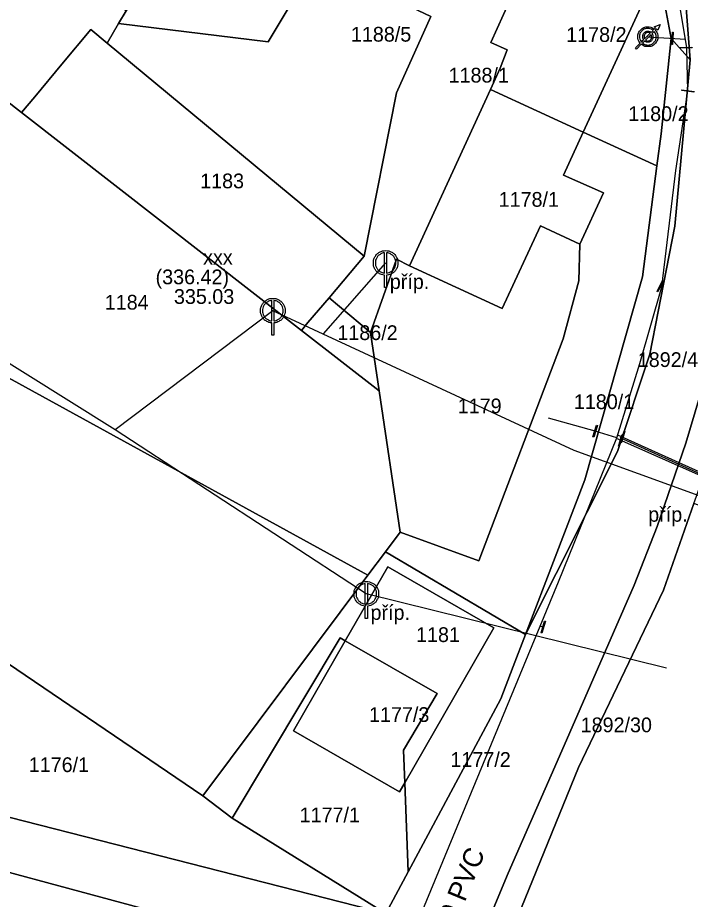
# Model space of a CAD drawing. Extents: x -559956 to -559707, y -1077221 to -1076919.
# Drawn here: x -559891.3 to -559822.9, y -1077119.6 to -1077029.9 of the extents above; entities that cross this region are included whole.
import ezdxf

# ---------------------------------------------------------------- set-up
doc = ezdxf.new("R2010")
doc.units = 0
for name, color, linetype in [('Armatura vodovodní', 7, 'Continuous'), ('Chránička', 7, 'Continuous'), ('Kanalizační přípojka', 7, 'Continuous'), ('Kanalizační šachta', 7, 'Continuous'), ('Odběrné místo', 7, 'Continuous'), ('Parcela-polygon', 7, 'Continuous'), ('Parcela-text', 7, 'Continuous'), ('Popis šachty', 7, 'Continuous'), ('Vodovodní přípojka', 7, 'Continuous'), ('Vodovodní řad', 7, 'Continuous'), ('Řad vodovodní popis', 7, 'Continuous')]:
    doc.layers.add(name, color=color, linetype=linetype)

msp = doc.modelspace()

# ---------------------------------------------------------------- linework, layer by layer
at = {"layer": 'Armatura vodovodní'}
for points in [[(-559824.59, -1077031.341), (-559824.668, -1077032.588), (-559824.746, -1077032.583), (-559824.667, -1077031.336), (-559824.59, -1077031.341)], [(-559823.938, -1077032.879), (-559822.689, -1077032.85), (-559822.687, -1077032.928), (-559823.936, -1077032.957), (-559823.938, -1077032.879)], [(-559823.709, -1077037.185), (-559822.473, -1077037.372), (-559822.485, -1077037.449), (-559823.721, -1077037.262), (-559823.709, -1077037.185)], [(-559826.238, -1077057.707), (-559825.679, -1077056.588), (-559825.61, -1077056.623), (-559826.169, -1077057.742), (-559826.238, -1077057.707)], [(-559832.312, -1077071.349), (-559832.681, -1077072.543), (-559832.756, -1077072.52), (-559832.386, -1077071.326), (-559832.312, -1077071.349)], [(-559829.706, -1077072.277), (-559830.078, -1077073.47), (-559830.152, -1077073.447), (-559829.78, -1077072.254), (-559829.706, -1077072.277)], [(-559829.522, -1077071.957), (-559829.901, -1077073.148), (-559829.976, -1077073.125), (-559829.597, -1077071.934), (-559829.522, -1077071.957)], [(-559838.022, -1077092.445), (-559837.673, -1077091.245), (-559837.598, -1077091.267), (-559837.947, -1077092.467), (-559838.022, -1077092.445)]]:
    msp.add_lwpolyline(points, dxfattribs=at)
at = {"layer": 'Chránička'}
msp.add_line((-559830.034, -1077072.562), (-559821.17, -1077076.58), dxfattribs=at)
at = {"layer": 'Kanalizační přípojka'}
for p, q in [((-559853.84, -1077054.814), (-559860.205, -1077062.042)), ((-559865.31, -1077059.67), (-559881.332, -1077071.786)), ((-559834.678, -1077073.906), (-559865.31, -1077059.67)), ((-559825.272, -1077096.049), (-559855.804, -1077088.477))]:
    msp.add_line(p, q, dxfattribs=at)
for points in [[(-559805.228, -1077048.435), (-559821.569, -1077078.649), (-559834.678, -1077073.906)], [(-559855.804, -1077088.477), (-559881.332, -1077071.786), (-559908.573, -1077054.768)]]:
    msp.add_lwpolyline(points, dxfattribs=at)
at = {"layer": 'Kanalizační šachta'}
for points in [[(-559853.943, -1077055.849), (-559853.943, -1077053.776)], [(-559853.737, -1077053.776), (-559853.737, -1077055.849)], [(-559853.737, -1077056.062), (-559853.737, -1077057.314), (-559853.943, -1077057.314), (-559853.943, -1077056.062)], [(-559865.413, -1077060.705), (-559865.413, -1077058.632)], [(-559865.207, -1077058.632), (-559865.207, -1077060.705)], [(-559865.207, -1077060.918), (-559865.207, -1077062.17), (-559865.413, -1077062.17), (-559865.413, -1077060.918)], [(-559855.907, -1077089.512), (-559855.907, -1077087.439)], [(-559855.701, -1077087.439), (-559855.701, -1077089.512)], [(-559855.701, -1077089.725), (-559855.701, -1077090.977), (-559855.907, -1077090.977), (-559855.907, -1077089.725)]]:
    msp.add_lwpolyline(points, dxfattribs=at)
for points in [[(-559853.943, -1077056.062), (-559854.201, -1077056.044), (-559854.463, -1077055.898), (-559854.76, -1077055.734), (-559854.925, -1077055.437), (-559855.09, -1077055.139), (-559855.09, -1077054.814), (-559855.09, -1077054.487), (-559854.922, -1077054.187), (-559854.753, -1077053.886), (-559854.455, -1077053.725), (-559854.157, -1077053.564), (-559853.84, -1077053.564), (-559853.525, -1077053.564), (-559853.226, -1077053.725), (-559852.927, -1077053.886), (-559852.758, -1077054.187), (-559852.59, -1077054.487), (-559852.59, -1077054.814), (-559852.59, -1077055.139), (-559852.755, -1077055.437), (-559852.92, -1077055.734), (-559853.217, -1077055.898), (-559853.479, -1077056.044), (-559853.737, -1077056.062)], [(-559853.943, -1077053.776), (-559854.14, -1077053.793), (-559854.355, -1077053.908), (-559854.604, -1077054.043), (-559854.743, -1077054.293), (-559854.882, -1077054.543), (-559854.882, -1077054.814), (-559854.882, -1077055.085), (-559854.746, -1077055.332), (-559854.609, -1077055.578), (-559854.36, -1077055.715), (-559854.148, -1077055.835), (-559853.943, -1077055.849)], [(-559853.737, -1077055.849), (-559853.532, -1077055.835), (-559853.318, -1077055.715), (-559853.071, -1077055.578), (-559852.934, -1077055.332), (-559852.798, -1077055.085), (-559852.798, -1077054.814), (-559852.798, -1077054.543), (-559852.938, -1077054.293), (-559853.078, -1077054.043), (-559853.327, -1077053.908), (-559853.54, -1077053.793), (-559853.737, -1077053.776)], [(-559865.413, -1077060.918), (-559865.671, -1077060.9), (-559865.933, -1077060.754), (-559866.23, -1077060.59), (-559866.395, -1077060.293), (-559866.56, -1077059.995), (-559866.56, -1077059.67), (-559866.56, -1077059.343), (-559866.392, -1077059.043), (-559866.223, -1077058.742), (-559865.925, -1077058.581), (-559865.627, -1077058.42), (-559865.31, -1077058.42), (-559864.995, -1077058.42), (-559864.696, -1077058.581), (-559864.397, -1077058.742), (-559864.228, -1077059.043), (-559864.06, -1077059.343), (-559864.06, -1077059.67), (-559864.06, -1077059.995), (-559864.225, -1077060.293), (-559864.39, -1077060.59), (-559864.687, -1077060.754), (-559864.949, -1077060.9), (-559865.207, -1077060.918)], [(-559865.413, -1077058.632), (-559865.61, -1077058.649), (-559865.825, -1077058.764), (-559866.074, -1077058.899), (-559866.213, -1077059.149), (-559866.352, -1077059.399), (-559866.352, -1077059.67), (-559866.352, -1077059.941), (-559866.216, -1077060.188), (-559866.079, -1077060.434), (-559865.83, -1077060.571), (-559865.618, -1077060.691), (-559865.413, -1077060.705)], [(-559865.207, -1077060.705), (-559865.002, -1077060.691), (-559864.788, -1077060.571), (-559864.541, -1077060.434), (-559864.404, -1077060.188), (-559864.268, -1077059.941), (-559864.268, -1077059.67), (-559864.268, -1077059.399), (-559864.408, -1077059.149), (-559864.548, -1077058.899), (-559864.797, -1077058.764), (-559865.01, -1077058.649), (-559865.207, -1077058.632)], [(-559855.907, -1077089.725), (-559856.165, -1077089.707), (-559856.427, -1077089.561), (-559856.724, -1077089.397), (-559856.889, -1077089.1), (-559857.054, -1077088.802), (-559857.054, -1077088.477), (-559857.054, -1077088.15), (-559856.886, -1077087.85), (-559856.717, -1077087.549), (-559856.419, -1077087.388), (-559856.121, -1077087.227), (-559855.804, -1077087.227), (-559855.489, -1077087.227), (-559855.19, -1077087.388), (-559854.891, -1077087.549), (-559854.722, -1077087.85), (-559854.554, -1077088.15), (-559854.554, -1077088.477), (-559854.554, -1077088.802), (-559854.719, -1077089.1), (-559854.884, -1077089.397), (-559855.181, -1077089.561), (-559855.443, -1077089.707), (-559855.701, -1077089.725)], [(-559855.907, -1077087.439), (-559856.104, -1077087.456), (-559856.319, -1077087.571), (-559856.568, -1077087.706), (-559856.707, -1077087.956), (-559856.846, -1077088.206), (-559856.846, -1077088.477), (-559856.846, -1077088.748), (-559856.71, -1077088.995), (-559856.573, -1077089.241), (-559856.324, -1077089.378), (-559856.112, -1077089.498), (-559855.907, -1077089.512)], [(-559855.701, -1077089.512), (-559855.496, -1077089.498), (-559855.282, -1077089.378), (-559855.035, -1077089.241), (-559854.898, -1077088.995), (-559854.762, -1077088.748), (-559854.762, -1077088.477), (-559854.762, -1077088.206), (-559854.902, -1077087.956), (-559855.042, -1077087.706), (-559855.291, -1077087.571), (-559855.504, -1077087.456), (-559855.701, -1077087.439)]]:
    msp.add_open_spline(points, degree=3, dxfattribs=at)
at = {"layer": 'Odběrné místo'}
for points in [[(-559826.528, -1077031.033), (-559826.4, -1077030.905)], [(-559826.4, -1077030.905), (-559826.518, -1077030.794), (-559825.931, -1077030.553), (-559826.153, -1077031.139), (-559826.29, -1077031.01), (-559826.421, -1077031.139)], [(-559827.506, -1077032.013), (-559826.943, -1077031.449)], [(-559826.851, -1077031.571), (-559827.419, -1077032.14)], [(-559826.849, -1077031.355), (-559826.647, -1077031.152)], [(-559826.539, -1077031.259), (-559826.748, -1077031.467)], [(-559827.842, -1077032.564), (-559828.33, -1077033.053), (-559828.431, -1077032.941), (-559827.948, -1077032.456)], [(-559827.828, -1077032.337), (-559827.609, -1077032.116)], [(-559827.512, -1077032.234), (-559827.722, -1077032.444)]]:
    msp.add_lwpolyline(points, dxfattribs=at)
for points in [[(-559827.948, -1077032.456), (-559828.188, -1077032.179), (-559828.188, -1077031.803), (-559828.188, -1077031.386), (-559827.893, -1077031.091), (-559827.598, -1077030.796), (-559827.179, -1077030.796), (-559826.804, -1077030.796), (-559826.528, -1077031.033)], [(-559826.647, -1077031.152), (-559826.874, -1077030.963), (-559827.179, -1077030.963), (-559827.528, -1077030.963), (-559827.774, -1077031.209), (-559828.02, -1077031.455), (-559828.02, -1077031.803), (-559828.02, -1077032.11), (-559827.828, -1077032.337)], [(-559826.421, -1077031.139), (-559826.171, -1077031.42), (-559826.171, -1077031.803), (-559826.171, -1077032.221), (-559826.466, -1077032.515), (-559826.761, -1077032.81), (-559827.179, -1077032.81), (-559827.562, -1077032.81), (-559827.842, -1077032.564)], [(-559827.722, -1077032.444), (-559827.493, -1077032.642), (-559827.179, -1077032.642), (-559826.831, -1077032.642), (-559826.584, -1077032.396), (-559826.338, -1077032.151), (-559826.338, -1077031.803), (-559826.338, -1077031.489), (-559826.539, -1077031.259)], [(-559827.609, -1077032.116), (-559827.617, -1077032.1), (-559827.624, -1077032.084), (-559827.687, -1077031.957), (-559827.687, -1077031.815), (-559827.687, -1077031.548), (-559827.543, -1077031.397), (-559827.399, -1077031.245), (-559827.172, -1077031.245), (-559827.024, -1077031.245), (-559826.904, -1077031.316), (-559826.875, -1077031.334), (-559826.849, -1077031.355)], [(-559826.943, -1077031.449), (-559826.96, -1077031.434), (-559826.98, -1077031.422), (-559827.065, -1077031.369), (-559827.172, -1077031.369), (-559827.322, -1077031.369), (-559827.431, -1077031.472), (-559827.54, -1077031.575), (-559827.54, -1077031.818), (-559827.54, -1077031.929), (-559827.506, -1077032.013)], [(-559826.748, -1077031.467), (-559826.733, -1077031.491), (-559826.721, -1077031.515), (-559826.659, -1077031.642), (-559826.659, -1077031.803), (-559826.659, -1077031.967), (-559826.725, -1077032.095), (-559826.791, -1077032.224), (-559826.912, -1077032.291), (-559827.032, -1077032.357), (-559827.173, -1077032.357), (-559827.324, -1077032.357), (-559827.444, -1077032.284), (-559827.48, -1077032.261), (-559827.512, -1077032.234)], [(-559827.419, -1077032.14), (-559827.319, -1077032.235), (-559827.174, -1077032.235), (-559827.013, -1077032.235), (-559826.909, -1077032.122), (-559826.805, -1077032.009), (-559826.805, -1077031.802), (-559826.805, -1077031.671), (-559826.849, -1077031.574), (-559826.851, -1077031.572), (-559826.851, -1077031.571)]]:
    msp.add_open_spline(points, degree=3, dxfattribs=at)
at = {"layer": 'Parcela-polygon'}
for points in [[(-559829.558, -1076918.773), (-559830.97, -1076923.33), (-559832.36, -1076934.35), (-559834.59, -1076966.73), (-559834.66, -1076971.24), (-559834.55, -1076971.98), (-559833.93, -1076976.03), (-559833.04, -1076981.92), (-559829.78, -1076982.61), (-559827.8, -1076995.29), (-559824.54, -1077015.89), (-559823.98, -1077019.58), (-559822.89, -1077034.16), (-559824.42, -1077051.06), (-559826.97, -1077064.1), (-559830.26, -1077074.01), (-559839.63, -1077092.62), (-559840.88, -1077095.88), (-559842.14, -1077099.15), (-559851.55, -1077116.77), (-559853.81, -1077121)], [(-559841.22, -1077123.3), (-559834.22, -1077106.14), (-559825.6, -1077088.11), (-559822.49, -1077079.28), (-559821.5, -1077076.46), (-559817.47, -1077065.01), (-559816.41, -1077060.26), (-559815.75, -1077057.31), (-559812.17, -1077041.3), (-559812.41, -1077037.94), (-559814.79, -1077038.97), (-559816.13, -1077040.49), (-559816.6, -1077041.94), (-559819.41, -1077058.74), (-559820.03, -1077061.65), (-559821.04, -1077065.52), (-559823.32, -1077073.15), (-559826.24, -1077081.64), (-559828.56, -1077087.59), (-559836.17, -1077104.99), (-559841.38, -1077116.88), (-559843.69, -1077122.42)], [(-559843.69, -1077122.42), (-559841.38, -1077116.88), (-559836.17, -1077104.99), (-559828.56, -1077087.59), (-559826.24, -1077081.64), (-559823.32, -1077073.15), (-559821.04, -1077065.52)], [(-559956.266, -1077180.273), (-559954.11, -1077184.61), (-559949.3, -1077185.88), (-559943.92, -1077169.97), (-559932.27, -1077137.8), (-559921.63, -1077108.87), (-559858.06, -1077126.03), (-559856.67, -1077126.39), (-559853.81, -1077121), (-559919.63, -1077104.19), (-559928.5, -1077099.87), (-559936.14, -1077093.02), (-559943.82, -1077086.65), (-559940.53, -1077082.73), (-559943.5, -1077080.07), (-559946.57, -1077077.52), (-559949.8, -1077075.14), (-559953.72, -1077072.62), (-559953.01, -1077070.87), (-559956.266, -1077070.49)]]:
    msp.add_lwpolyline(points, dxfattribs=at)
for points in [[(-559871.91, -1077015.38), (-559880.21, -1077029.16), (-559880.99, -1077030.45), (-559865.8, -1077032.33), (-559851.62, -1077008.67), (-559864.6, -1077003.43), (-559868.25, -1077009.31)], [(-559888.94, -1077008.18), (-559902.26, -1077026.17), (-559897.39, -1077030), (-559899.67, -1077032.65), (-559890.87, -1077039.51), (-559889.51, -1077037.9), (-559886.76, -1077034.59), (-559883.82, -1077031.07), (-559882.16, -1077032.46), (-559880.99, -1077030.45), (-559880.21, -1077029.16), (-559888.42, -1077024.31), (-559880.14, -1077010.46)], [(-559851.19, -1077028.84), (-559846.79, -1077019.15), (-559844.72, -1077014.6), (-559826.54, -1077022.53), (-559827.3, -1077018.35), (-559851.62, -1077008.67), (-559865.8, -1077032.33), (-559880.99, -1077030.45), (-559882.16, -1077032.46), (-559856.03, -1077054.13), (-559852.74, -1077037.52), (-559849.23, -1077029.74)], [(-559844.72, -1077014.6), (-559846.79, -1077019.15), (-559851.19, -1077028.84), (-559849.23, -1077029.74), (-559852.74, -1077037.52), (-559856.03, -1077054.13), (-559859.59, -1077058.36), (-559855.38, -1077061.9), (-559852.72, -1077054.42), (-559851.42, -1077055.1), (-559843.19, -1077037.18), (-559842.18, -1077034.99), (-559841.49, -1077033.13), (-559843.15, -1077032.38), (-559837.99, -1077020.96), (-559836.12, -1077021.81), (-559826.67, -1077026.12), (-559825.81, -1077026.51), (-559826.54, -1077022.53)], [(-559827.3, -1077018.35), (-559826.54, -1077022.53), (-559825.81, -1077026.51), (-559824.81, -1077031.97), (-559822.89, -1077034.16), (-559823.98, -1077019.58)], [(-559843.19, -1077037.18), (-559833.75, -1077041.51), (-559832.73, -1077039.29), (-559826.67, -1077026.12), (-559836.12, -1077021.81), (-559837.99, -1077020.96), (-559843.15, -1077032.38), (-559841.49, -1077033.13), (-559842.18, -1077034.99)], [(-559826.67, -1077026.12), (-559832.73, -1077039.29), (-559833.75, -1077041.51), (-559826.26, -1077044.95), (-559825.83, -1077041.69), (-559824.81, -1077031.97), (-559825.81, -1077026.51)], [(-559882.16, -1077032.46), (-559883.82, -1077031.07), (-559886.76, -1077034.59), (-559889.51, -1077037.9), (-559890.87, -1077039.51), (-559862.41, -1077061.67), (-559861.74, -1077060.88), (-559859.59, -1077058.36), (-559856.03, -1077054.13)], [(-559824.81, -1077031.97), (-559825.83, -1077041.69), (-559826.26, -1077044.95), (-559827.73, -1077056.24), (-559833.58, -1077076.88), (-559839.63, -1077092.62), (-559830.26, -1077074.01), (-559826.97, -1077064.1), (-559824.42, -1077051.06), (-559822.89, -1077034.16)], [(-559853.86, -1077084.2), (-559852.37, -1077082.21), (-559854.5, -1077067.83), (-559862.41, -1077061.67), (-559890.87, -1077039.51), (-559899.67, -1077032.65), (-559917.05, -1077052.87), (-559855.64, -1077086.59)], [(-559843.19, -1077037.18), (-559851.42, -1077055.1), (-559841.99, -1077059.45), (-559838.09, -1077051.04), (-559834.08, -1077052.9), (-559831.68, -1077047.67), (-559835.75, -1077045.87), (-559833.75, -1077041.51)], [(-559839.63, -1077092.62), (-559833.58, -1077076.88), (-559827.73, -1077056.24), (-559826.26, -1077044.95), (-559833.75, -1077041.51), (-559835.75, -1077045.87), (-559831.68, -1077047.67), (-559834.08, -1077052.9), (-559834.2, -1077056.64), (-559835.78, -1077062.54), (-559844.36, -1077085.13), (-559852.37, -1077082.21), (-559853.86, -1077084.2)], [(-559838.09, -1077051.04), (-559841.99, -1077059.45), (-559851.42, -1077055.1), (-559852.72, -1077054.42), (-559855.38, -1077061.9), (-559854.5, -1077067.83), (-559852.37, -1077082.21), (-559844.36, -1077085.13), (-559835.78, -1077062.54), (-559834.2, -1077056.64), (-559834.08, -1077052.9)], [(-559918.33, -1077079), (-559914.1, -1077081.1), (-559906.71, -1077085.76), (-559872.43, -1077109.04), (-559855.64, -1077086.59), (-559917.05, -1077052.87), (-559934.19, -1077072.71), (-559928.12, -1077074.97)], [(-559861.74, -1077060.88), (-559862.41, -1077061.67), (-559854.5, -1077067.83), (-559855.38, -1077061.9), (-559859.59, -1077058.36)], [(-559786.96, -1077091.88), (-559822.49, -1077079.28), (-559825.6, -1077088.11), (-559834.22, -1077106.14), (-559841.22, -1077123.3), (-559838.86, -1077123.92), (-559816.84, -1077129.72), (-559808.49, -1077127.23), (-559802.04, -1077120.75), (-559794.15, -1077102.35)], [(-559919.63, -1077104.19), (-559853.81, -1077121), (-559869.45, -1077111.31), (-559872.43, -1077109.04), (-559906.71, -1077085.76), (-559914.1, -1077081.1)], [(-559839.63, -1077092.62), (-559853.86, -1077084.2), (-559855.64, -1077086.59), (-559872.43, -1077109.04), (-559869.45, -1077111.31), (-559858.47, -1077092.97), (-559857.96, -1077093.26), (-559853.63, -1077085.72), (-559842.84, -1077091.95), (-559851.9, -1077107.71), (-559851.55, -1077116.77), (-559842.14, -1077099.15), (-559840.88, -1077095.88)], [(-559842.84, -1077091.95), (-559853.63, -1077085.72), (-559857.96, -1077093.26), (-559848.59, -1077098.63), (-559852.03, -1077104.38), (-559851.9, -1077107.71)], [(-559863.22, -1077102.43), (-559857.96, -1077093.26), (-559858.47, -1077092.97), (-559869.45, -1077111.31), (-559853.81, -1077121), (-559851.55, -1077116.77), (-559851.9, -1077107.71), (-559852.42, -1077108.61)], [(-559848.59, -1077098.63), (-559857.96, -1077093.26), (-559863.22, -1077102.43), (-559852.42, -1077108.61), (-559851.9, -1077107.71), (-559852.03, -1077104.38)], [(-559921.63, -1077108.87), (-559932.27, -1077137.8), (-559867.06, -1077160.72), (-559858.06, -1077126.03)]]:
    msp.add_lwpolyline(points, close=True, dxfattribs=at)
at = {"layer": 'Vodovodní přípojka'}
for p, q in [((-559827.181, -1077031.803), (-559823.346, -1077032.046)), ((-559825.742, -1077057.256), (-559825.924, -1077057.165)), ((-559821.285, -1077076.37), (-559830.236, -1077072.321)), ((-559837.81, -1077091.856), (-559838.13, -1077091.763))]:
    msp.add_line(p, q, dxfattribs=at)
for points in [[(-559806.009, -1077070.723), (-559805.825, -1077069.987), (-559810.053, -1077068.517), (-559819.428, -1077077.524), (-559830.353, -1077072.674)], [(-559830.322, -1077072.597), (-559832.534, -1077071.935), (-559837.272, -1077070.607)]]:
    msp.add_lwpolyline(points, dxfattribs=at)
at = {"layer": 'Vodovodní řad'}
msp.add_line((-559823.097, -1077037.317), (-559823.196, -1077033.065), dxfattribs=at)
for points in [[(-559823.196, -1077033.065), (-559823.2, -1077032.897), (-559824.212, -1077026.979), (-559826.19, -1077016.537), (-559829.603, -1076991.495), (-559831.972, -1076974.117)], [(-559855.58, -1077135.364), (-559854.608, -1077131.63), (-559836.262, -1077087.244), (-559830.322, -1077072.597), (-559827.987, -1077065.052), (-559825.742, -1077057.256), (-559824.328, -1077045.425), (-559823.097, -1077037.317)]]:
    msp.add_lwpolyline(points, dxfattribs=at)

# ---------------------------------------------------------------- texts
at = {"layer": 'Parcela-text'}
for s, p in [('1188/5', (-559857.37, -1077032.3)), ('1178/2', (-559835.48, -1077032.33)), ('1188/1', (-559847.44, -1077036.46)), ('1180/2', (-559829.17, -1077040.38)), ('1183', (-559872.7, -1077047.22)), ('1178/1', (-559842.35, -1077049.1)), ('1184', (-559882.4, -1077059.56)), ('1186/2', (-559858.75, -1077062.66)), ('1892/4', (-559828.2, -1077065.4)), ('1179', (-559846.51, -1077070.11)), ('1180/1', (-559834.7, -1077069.68)), ('1181', (-559850.75, -1077093.38)), ('1177/3', (-559855.53, -1077101.51)), ('1892/30', (-559834.01, -1077102.56)), ('1177/2', (-559847.25, -1077106.08)), ('1176/1', (-559890.13, -1077106.61)), ('1177/1', (-559862.59, -1077111.72))]:
    msp.add_text(s, height=1.5, dxfattribs=at).set_placement(p)
at = {"layer": 'Popis šachty'}
for s, p in [('xxx', (-559872.399, -1077054.981)), ('(336.42)', (-559877.233, -1077056.981)), ('příp.', (-559853.414, -1077057.462)), ('335.03', (-559875.367, -1077058.981)), ('příp.', (-559827.141, -1077081.145)), ('příp.', (-559855.378, -1077091.125))]:
    msp.add_text(s, height=1.5, dxfattribs=at).set_placement(p)
at = {"layer": 'Řad vodovodní popis'}
msp.add_text(' 160 PVC', height=2, rotation=67.5433, dxfattribs=at).set_placement((-559848.065, -1077125.4))

doc.saveas('drawing.dxf')
